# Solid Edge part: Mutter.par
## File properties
Sűrűség: 0,000 kg/m^3
Pontosság: 0,990
Author: ahadarics
Last saved by: psaghy
Revision: 77
Username: ahadarics
Dokumentum tartalom típus: 0
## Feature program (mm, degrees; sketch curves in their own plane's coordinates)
base feature "unnamed BaseFeature 1"
sketch for "Furat_1" plane through (9, 0, 0) normal (1, 0, 0) x-axis (0, 1, 0)
hole "Furat_1" diameter 20 through  StartChamferOffset = 0.47 mm; StartChamferAngle = 45 deg
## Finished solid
Body 1: solid body, 23 faces, 47 edges, 26 vertices.
  Faces by surface: cone 14, plane 8, cylinder 1
  Edges by curve: spline 24, circle 16, line 7
Bounding box of the edges (mm): 9.000 x 34.641 x 30.000, from (0, -17.3205, -15) to (9, 17.3205, 15).
Cylindrical faces by radius (mm): R9.188 x1
Conical faces (half-angle, radius in mm at the cone's reference point): 45 deg R9.658 x1, 60 deg R9.5939 x1, 60 deg R16.1603 x12
Planar faces by outward normal: +x 1, +z 1, -x 1, -z 1, oblique 4
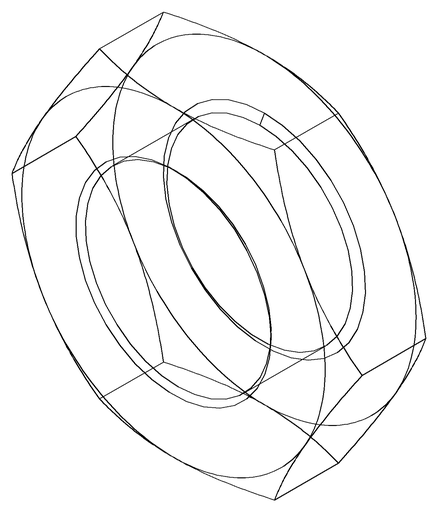
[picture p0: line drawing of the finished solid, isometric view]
